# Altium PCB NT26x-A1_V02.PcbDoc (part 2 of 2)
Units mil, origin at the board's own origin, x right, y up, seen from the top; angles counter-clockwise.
Board outline 1026.77 x 2401.57 mil, 4 copper layers (Top Layer 1, GND2, POWER3, Bottom Layer 4), stack 61.855 mil thick; 87 components, 81 nets, 679 pads, 247 vias.
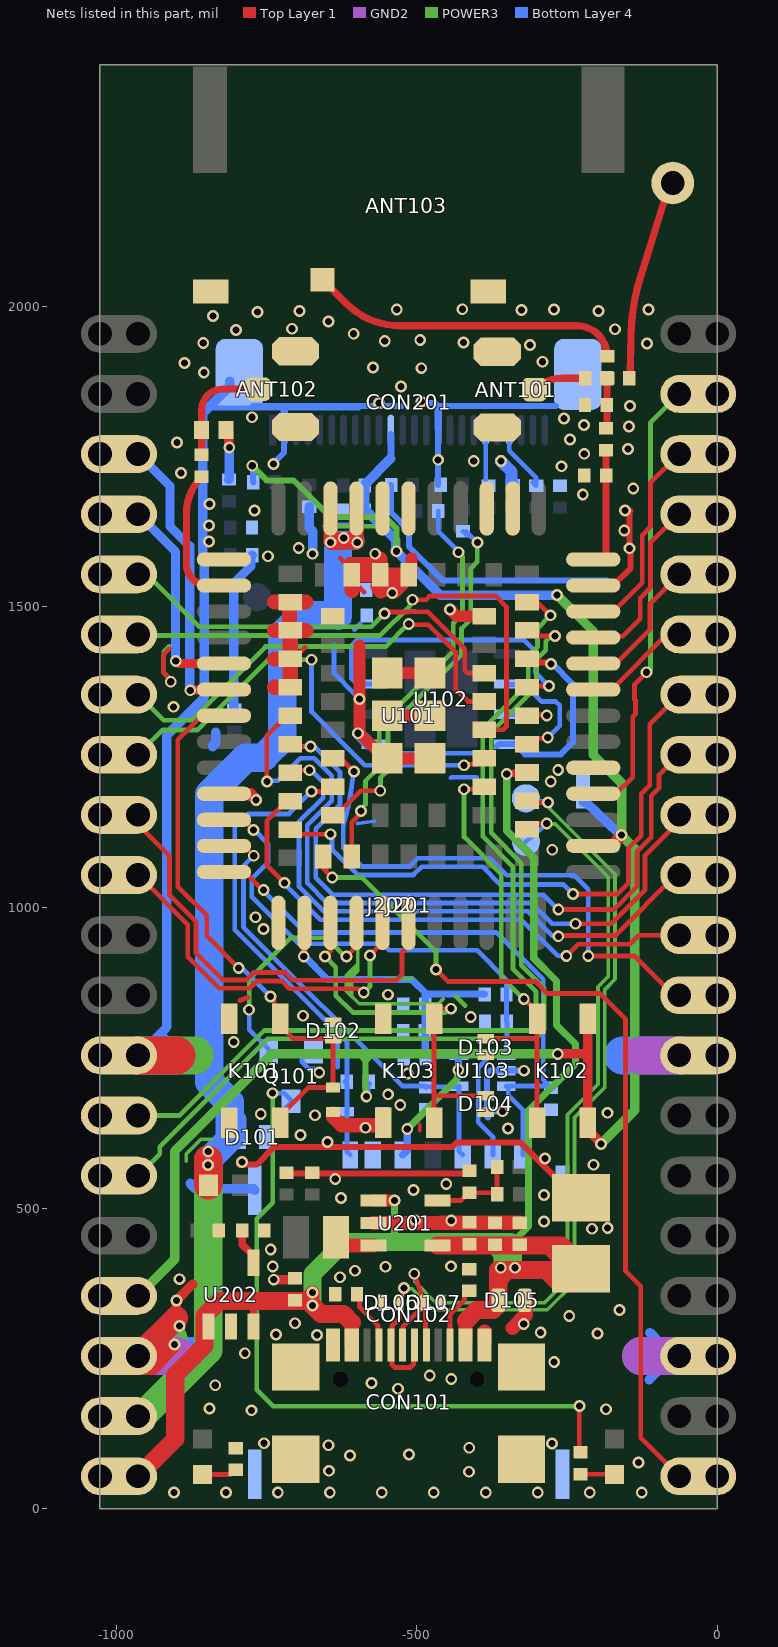
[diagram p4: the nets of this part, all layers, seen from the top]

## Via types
v1: diameter 19.68, hole 11.81, Top Layer 1 to Bottom Layer 4, tented both sides, 247 vias

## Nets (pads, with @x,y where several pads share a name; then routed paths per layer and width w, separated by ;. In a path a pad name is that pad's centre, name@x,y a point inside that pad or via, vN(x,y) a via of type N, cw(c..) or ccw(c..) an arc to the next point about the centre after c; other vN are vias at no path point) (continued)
GND: ANT101.2 ANT101.3 ANT102.2 ANT102.3 ANT103.2 C101.1 C102.1 C103.1 C104.1 C105.1 C109.1 C110.1 C112.1 C113.1 C114.1 C115.1 C116.1 C117.1 C118.1 C119.1 C202.1 C203.1 C204.2 C205.1 C206.1 C207.1 C208.1 C209.1 C210.1 C211.2 C212.2 C213.1 C214.1 C215.1 C216.1 CON101.0@-325.59,82.19 CON101.0@-325.59,235.73 CON101.0@-701.18,82.19 CON101.0@-701.18,235.73 CON101.A1B12 CON101.B1A12 CON102.0@-257.48,57.38 CON102.0@-257.48,529.82 CON102.0@-769.29,57.38 CON102.0@-769.29,529.82 CON102.5 CON201.0 CON201.2 CON201.15 D101.A D102.A D103.A D104.A D105.A D106.A D107.A D108.K J201.3 J201.8 J202.33 J202.38 K101.1 K101.2 K103.1 K103.2 P101.2 Q101.E R106.1 R107.1 R203.2 R204.2 U101.1@-820.47,1578.74 U101.10@-820.47,1188.98 U101.27@-206.3,1232.28 U101.34@-206.3,1535.43 U101.36@-340.16,1663.39 U101.37@-383.46,1663.39 U101.40@-513.39,1663.39 U101.41@-556.69,1663.39 U101.45@-710.24,1507.87 U101.46@-710.24,1460.63 U101.47@-710.24,1413.39 U101.48@-710.24,1366.14 U101.70@-513.39,1553.15 U101.71@-560.63,1553.15 U101.72@-607.87,1553.15 U101.73@-639.37,1484.25 U101.88@-387.4,1484.25 U101.89@-548.82,1389.76 U101.90@-548.82,1318.9 U101.91@-548.82,1248.03 U101.92@-477.95,1248.03 U101.93@-477.95,1318.9 U101.94@-477.95,1389.76 U101.95@-729.92,974.41 U102.1 U103.2 U201.2 U202.2 | length 8528.6
  Top Layer 1 w6: -494.92,639.05 -494.79,629
  Top Layer 1 w7.87: -911.09,1430.22 -920.47,1420.84 -920.47,1389.92 -909.04,1378.48 v1(-909.04,1375.29) ; U101.47@-700.03,1418.02 -685.89,1432.17 ; -627.03,1581.02 U101.72@-612.89,1566.88 ; U101.72@-601.81,1538.89 -587.67,1524.75
  Top Layer 1 w8: -794.05,845.19 -780.33,850.42
  Top Layer 1 w10: v1@-795.7,574.97 -795.7,572.35 -766.08,572.35 -736.52,601.92 -440.49,601.92 -433.72,608.68 -327,608.68 -235.32,517 C204.2@-226.46,517 ; C203.1@-716.6,557.45 -645.12,557.45 -644.69,557.87 -416.29,557.87 R203.2@-412.34,561.81 ; U101.88@-388.83,1485.68 U101.88@-387.4,1484.25 ; U101.34@-206.3,1535.43 -172.83,1535.43 -143.97,1564.3 -143.97,1574.3 -144.36,1574.69 -144.36,1595.37 v1(-146.22,1597.22) -146.22,1657.22 v1@-143.97,1659.46
  Top Layer 1 w11.81: J202.38@-987.07,228.5 -937.29,228.5 v1@-899.21,266.57 ; J202.38@-942.12,236.14 -913.15,265.11 ; J202.38@-941,247.71 -912.02,276.69
  Top Layer 1 w15.75: -899.66,317.66 v1(-899.66,346.39) -872.51,373.54 ; v1(-737.63,380.88) -704.66,380.88 C208.1@-702.2,383.34 C208.1@-700.17,385.38
  Top Layer 1 w19.68: v1(-444.48,1495.68) -433.06,1484.25 U101.88@-387.4,1484.25
  Top Layer 1 w20: U101.10@-820.47,1188.98 -819.78,1188.28 -776.32,1188.28 v1(-766.91,1178.88) ; U101.72@-611.33,1572.74 U101.71@-572.81,1572.74 ; -595.12,1435.38 v1(-595.12,1346.43) -595.12,1289.64 U101.91@-554.97,1249.49 ; U101.71@-560.01,1540.11 -566.82,1533.3 -560.32,1533.3 -560.01,1533 -552.91,1525.9 v1@-539.56,1525.9 ; U101.91@-548.82,1248.03 U101.92@-492.03,1248.03 ; U101.90@-548.82,1318.9 U101.93@-492.03,1318.9 ; U101.89@-548.82,1389.76 U101.94@-492.03,1389.76 ; -548.06,1530.92 -529.65,1549.33 ; v1@-536,1524.12 U101.70@-517.59,1542.53 ; U101.70@-508.61,1553.9 -508.61,1579.93
  Top Layer 1 w23.62: P101.2@-638.96,656.89 -638.96,651.63 -625.13,637.79 K103.1@-569.3,637.79 ; U201.2@-571.95,475.08 v1@-507.77,475.08 ; v1@-499.3,475.08 -459.74,475.08 -459.38,475.44 C206.1@-369.91,475.44 C205.1@-328.56,475.44 ; CON101.B1A12@-387.4,277.46 CON101.B1A12@-387.4,294.19 ; -340.66,300.62 -318.62,322.67 D105.A@-318.62,354.43
  Top Layer 1 w25: -736.27,1366.14 U101.48@-710.24,1366.14 U101.47@-710.24,1413.39 ; -736.27,1413.39 U101.47@-710.24,1413.39 ; -736.27,1460.63 U101.46@-711.67,1460.63 ; -736.27,1507.87 U101.45@-711.67,1507.87 ; U101.45@-711.67,1508.09 U101.45@-711.67,1507.87 ; -684.2,1460.63 U101.46@-710.24,1460.63 ; -684.2,1507.87 U101.45@-710.24,1507.87 U101.45@-711.67,1507.87 ; -607.87,1527.12 U101.72@-607.87,1553.15 U101.71@-560.63,1553.15 ; -560.63,1579.18 U101.71@-560.63,1553.15 ; -560.01,1526.5 -560.01,1533 -560.01,1540.11 -560.01,1552.53 U101.71@-560.63,1553.15 ; U101.71@-560.01,1553.15 U101.70@-513.39,1553.15 ; U101.46@-711.67,1460.63 U101.45@-711.67,1507.87 ; U101.46@-711.67,1460.63 U101.46@-710.24,1460.63 ; U101.47@-710.24,1413.39 U101.46@-710.24,1460.63
  Top Layer 1 w39.37: J202.38@-963.39,253.94 -899.66,317.66
  Top Layer 1 w62.99: J202.33@-963.39,753.94 -899.4,753.94
  GND2 w62.99: J202.38@-963.39,253.94 -899.4,253.94 ; J202.33@-963.39,753.94 -899.4,753.94 ; -127.37,253.94 J201.3@-63.39,253.94 ; -127.37,753.94 J201.8@-63.39,753.94
  POWER3 w5.98: -883.12,577.57 -883.12,589.86 -858.24,614.74 -840.88,614.74 ; -612.5,860.08 -612.5,886.39 ; -612.35,886.72 -602.16,896.92 ; -608.37,852.81 -608.37,883.66 -598.18,893.86 -598.18,905.86 ; -597.84,938.76 -598.08,938.53 -598.08,910.73 -598.18,910.63 -598.18,905.86 ; -547.93,881.07 -507.32,881.07 ; -456.24,847.77 -464.27,839.74 -595.71,839.74 -616.85,860.88 -616.85,887.19 -598.18,905.86
  POWER3 w7.87: -911.32,1434.27 -920.47,1425.12 -920.47,1389.92 -909.04,1378.48 v1(-909.04,1375.29) ; -652.9,1633.98 -561.16,1633.98 -551.08,1623.9 ; -435.32,852.29 -419.43,836.4
  POWER3 w51.18: J202.38@-975.53,249.42 -940.26,249.42 -906.72,282.97
  POWER3 w62.99: J202.33@-963.39,753.94 -869.46,753.94 ; -120.68,253.94 J201.3@-63.39,253.94
  Bottom Layer 4 w6: -598.75,1139.61 -569.89,1143.59
  Bottom Layer 4 w7.87: -844.62,1830.5 -724.62,1830.5 ; -715.54,1830.5 -595.53,1830.5 ; -652.9,1633.98 -650.51,1636.37 -590.08,1636.37 ; -637.36,1436.72 -637.36,1389.06 -603.12,1354.83 ; -603.62,1462.08 -594.21,1471.5 ; -536.18,1256.21 -399.96,1256.21 ; -442.71,1215.67 -442.01,1216.37 -400.27,1216.37
  Bottom Layer 4 w8: -690.89,747.15 -690.89,743.21 -679.14,731.46 -670.86,731.46 -665.12,725.71 v1(-661.95,725.71) ; -631.73,734.47 -631.73,771.84 ; -522.51,1491.75 -502.38,1491.75
  Bottom Layer 4 w10: CON201.0@-773.05,1833.55 -523.99,1833.55 ; v1(-738.09,1737.66) -738.09,1738.75 -720.27,1756.57 -720.27,1786.22 CON201.2@-720.08,1786.42 ; C213.1@-542.54,1702.63 -542.54,1656.71 -512.87,1627.04 -512.87,1600.18 -455.99,1543.3 -183.5,1543.3 -183.04,1543.76 ; v1(-492.17,1841.11) -490.31,1839.25 -469.88,1839.25 -464.17,1833.55 CON201.0@-267.94,1833.55 ; C214.1@-464.28,1702.4 -464.23,1702.45 v1(-464.23,1744.41) -464.23,1786.36 -464.17,1786.42 CON201.15@-464.17,1795.1 ; -381.62,650.83 -382.68,651.9 -382.68,724.1 -379.33,727.44 ; -376.82,660.93 v1(-357.45,660.93) ; -376.82,728.47 U103.2@-350.96,728.47 v1(-321.44,728.47)
  Bottom Layer 4 w12: CON201.2@-720.27,1786.61 -720.27,1831.86 ; CON201.15@-464.17,1795.1 -464.17,1827.49 -464.17,1831.2
  Bottom Layer 4 w15.75: J202.33@-981.61,730.94 -935.43,730.94 -914.44,751.93 ; J202.33@-963.39,768.84 -947.23,768.84 -917.39,798.68 ; J202.33@-937.02,747.74 -921.93,762.83 ; -933.73,766.35 -918.64,781.44 ; -915.37,801.95 -915.37,1286.68 -852.89,1349.16 -852.89,1585.52 -855.43,1588.06 -855.43,1635.2 -855.43,1822.33 -850.23,1827.52 -810.63,1867.13 CON201.0@-810.63,1875 ; -876.75,541.03 -867.53,531.8 -771.27,531.8 CON102.0@-769.29,529.82 ; -839.36,1267.43 -839.36,1268.91 -834.44,1273.83 -834.44,1291.45 ; C112.1@-804.09,1326.84 -804.09,1539.23 -775.9,1567.43 -775.9,1583.1 C104.1@-773.44,1585.56 ; C211.2@-678.68,1666.44 -678.4,1666.16 -678.4,1631.24 -673.14,1625.98 v1(-673.14,1588.08) ; -113.25,214.7 -98.16,229.79 ; -112.14,292.83 -97.05,277.73
  Bottom Layer 4 w20: v1(-597.7,1289.64) -597.47,1289.64 U102.1@-579.4,1271.57 ; v1(-359.79,1742.43) -359.79,1742.25 -341.93,1724.39 -341.93,1702.58 -341.59,1702.25 C215.1@-340.12,1702.25
  Bottom Layer 4 w62.99: J202.38@-963.39,253.94 -869.46,253.94 ; -157.31,753.94 J201.8@-63.39,753.94 ; J201.3@-91.82,253.94 J201.3@-63.39,253.94
  other v1: -903.8,26.8 -817.34,26.8 -730.89,26.8 -644.43,26.8 -557.97,26.8 -471.52,26.8 -385.06,26.8 -298.61,26.8 -212.15,26.8 -125.69,26.8 -412.9,61.4 -645.74,63.02 -131.05,76.87 -610.8,88.63 -512.49,90.13 -412.46,101.47 -646.41,105.5 -753.67,108.92 -274.74,108.56 -774.47,163.65 -185.01,165.41 -844.79,166.57 -530.9,199.57 -835.03,205.29 -575.34,209.09 -442.4,215.9 -478.18,221.36 -271.28,244.12 -785.77,258.48 -902.68,272.98 -665.46,288.96 -734.18,289.65 -199,291.21 -293.74,293.07 -894.69,303.78 -321.85,307.06 -702.47,308.48 -246.16,320.54 -162.86,330.24 -894.3,381.74 -627.26,385.01 -602.78,395.79 -552.05,402.33 -739.25,403.09 -443.09,403.14 -742.77,431.15 -208.25,465.67 -182.31,466.66 -288.21,477.9 -442.48,479.06 -502.38,479.83 -625.75,516.77 -288.21,521.77 -505.1,529.85 -450.86,540.28 -635.36,548.45 -206.15,572.01 -790.23,576.52 -286.49,582.16 -648.16,609.97 -693.08,621.29 -348.22,632.55 -585,633.63 -669.21,654.32 -759.27,656.59 -182.68,658.43 -527.22,671.66 -547.37,689.17 -514.9,723.71 -804.16,776.08 -410.06,817.85 -689.09,819.81 -547.51,854.87 -754.5,964.01 -768.25,983.62 -274.47,1095.88 -276.94,1209.3 -264.61,1228.8 -904.45,1333.61 -540.65,1522.75 -747.1,1583.98 -568.97,1588.13 -696.05,1597.67 -845.5,1608.42 -154.73,1626.73 -845.32,1635.2 -769.73,1660.3 -153.56,1660.26 -844.79,1670.79 -223.67,1686.7 -139.71,1696.65 -891.82,1722.49 -258.98,1733.59 -405.04,1742.43 -221.33,1754.36 -148.47,1762.41 -898.82,1772.95 -244.85,1778.39 -146.8,1799.66 -221.84,1802.17 -255.16,1813.17 -773.77,1815.24 -145.11,1834.1 -562.88,1839.1 -526.12,1866.59 -854,1889.48 -492.27,1896.81 -572.5,1897.9 -886.25,1905.58 -290.63,1907.47 -311.44,1935.53 -854.96,1938.4 -116.93,1937.76 -421.98,1939.28 -553.11,1941.97 -494.12,1943.66 -604.75,1954.06 -800.58,1960.47 -170.4,1961.49 -707.22,1962.4 -646.51,1974.23 -838.89,1983.62 -764.51,1990.25 -694.93,1992.09 -197.56,1991.93 -325.58,1993.53 -533.17,1994.47 -271.61,1994.35 -424.07,1994.87 -114.39,1994.55
I2C_SCL: J202.34 U101.67@-316.54,1507.87 | length 1571
  Top Layer 1 w7.87: U101.67@-308.89,1500.22 U101.67@-316.54,1507.87 -299.72,1507.87 v1(-277.64,1485.79)
  POWER3 w7.87: J202.34@-995.08,653.94 J202.34@-979.23,669.78 ; J202.34@-963.39,653.94 -894.85,653.94 -753.48,795.31 -309.09,795.31 -301.46,802.94 -301.46,859.93 -339.78,898.25 -339.78,1067.87 -389.99,1118.07 -389.99,1296.69 -314.56,1372.11 -314.56,1417.78 -298.99,1433.35 -298.99,1464.44 v1(-277.64,1485.79)
I2C_SDA: J202.35 U101.66@-316.54,1460.63 | length 1573
  Top Layer 1 w7.87: U101.66@-316.54,1460.63 -307.16,1451.25 v1(-269.73,1451.25)
  POWER3 w7.87: J202.35@-963.39,553.94 -927.44,589.88 -927.44,601.75 -747.74,781.45 -303.17,781.45 -287.61,797.01 -287.61,865.67 -325.92,903.99 -325.92,1073.61 -376.13,1123.81 -376.13,1290.95 -300.7,1366.37 -300.7,1412.04 -285.13,1427.61 -285.13,1442.56 -278.69,1448.99 -271.99,1448.99 v1(-269.73,1451.25)
I2S_BCK: J201.15 U101.30@-206.3,1362.2 | length 195.8
  Top Layer 1 w7.87: U101.30@-206.3,1362.2 -175.79,1362.2 -84.05,1453.94 J201.15@-63.39,1453.94 J201.15@-73.93,1443.39
I2S_DIN: J201.17 U101.32@-206.3,1448.82 | length 291.6
  Top Layer 1 w7.87: U101.32@-206.3,1448.82 -204.02,1451.09 -157.45,1451.09 -128.12,1480.43 -128.12,1514.51 -111.13,1531.5 -111.13,1606.19 J201.17@-63.39,1653.94
I2S_DOUT: J201.18 U101.33@-206.3,1492.13 | length 340.6
  Top Layer 1 w7.87: U101.33@-206.3,1492.13 -172.83,1492.13 -124.99,1539.97 -124.99,1619.26 -111.13,1633.12 -111.13,1706.19 J201.18@-63.39,1753.94
I2S_LRCK: J201.16 U101.31@-206.3,1405.51 | length 229.5
  Top Layer 1 w7.87: U101.31@-206.3,1405.51 -168.89,1405.51 -111.91,1462.49 -111.91,1505.41 J201.16@-63.39,1553.94
I2S_MCLK: J201.19 U101.26@-206.3,1188.98 | length 749
  Top Layer 1 w7.87: U101.26@-206.3,1188.98 -168.57,1188.98 -140.79,1216.76 -140.79,1317.02 -135.97,1321.84 -135.97,1344.03 -137.58,1345.64 -137.58,1371.02 v1(-117.56,1391.04)
  POWER3 w7.87: v1(-117.56,1391.04) -115.21,1391.04 -111.13,1395.12 -111.13,1806.19 J201.19@-63.39,1853.94
LCD_CLK: J201.14 U101.53@-710.36,1129.47 | length 992
  Top Layer 1 w7.87: U101.53@-710.36,1129.47 -702.68,1121.79 v1(-643.13,1121.79) ; v1(-240.1,1022.46) -165.95,1022.46 -147.88,1040.53 -147.88,1097.99 -126.27,1119.59 -126.27,1189.05 -112.38,1202.94 -112.38,1304.94 -70.85,1346.47 -70.85,1353.94 J201.14@-63.39,1353.94
  Bottom Layer 4 w7.87: v1(-643.13,1121.79) -640.87,1119.53 -640.87,1096.53 -598.33,1054 -505.43,1054 -491.58,1067.84 -390.48,1067.84 -360.75,1038.11 -255.75,1038.11 v1(-240.1,1022.46)
LCD_CS: J201.10 U101.52@-710.36,1176.72 | length 921.2
  Top Layer 1 w7.87: v1(-719.9,1040.92) -748.94,1069.96 -748.94,1144.04 -716.27,1176.72 U101.52@-710.36,1176.72 ; v1(-251.1,919.05) -231.28,938.87 -145.67,938.87 -130.61,953.94 J201.10@-63.39,953.94 J201.10@-31.69,953.94
  Bottom Layer 4 w7.87: v1(-719.9,1040.92) -719.9,1039.5 -660,979.61 -325.69,979.61 -265.55,919.47 -251.52,919.47 v1(-251.1,919.05)
LCD_DOUT: J201.13 U101.50@-710.36,1271.2 | length 1115.4
  Top Layer 1 w7.87: U101.50@-710.36,1271.2 -705.82,1266.66 -704.69,1267.79 v1(-676.7,1267.79) ; v1(-264.39,996.38) -172.42,996.38 -134.02,1034.79 -134.02,1092.25 -109.92,1116.34 -109.92,1185.8 -96.79,1198.93 -96.79,1220.53 J201.13@-63.39,1253.94
  Bottom Layer 4 w7.87: v1(-676.7,1267.79) -670.5,1267.79 -627.43,1224.72 -627.43,1171.25 -667.99,1130.69 -667.99,1049.58 -639.6,1021.18 -289.19,1021.18 v1(-264.39,996.38)
LCD_RS: J201.11 U101.51@-710.36,1223.96 | length 967.5
  Top Layer 1 w7.87: U101.51@-710.36,1223.96 -706.21,1228.11 v1(-678.37,1228.11) ; v1@-266.01,958.91 -260.22,953.12 -170.14,953.12 -69.32,1053.94 J201.11@-63.39,1053.94
  Bottom Layer 4 w7.87: v1(-678.37,1228.11) -675.46,1228.11 -655.14,1207.79 -655.14,1182.73 -695.71,1142.17 -695.71,1034.91 -654.26,993.46 -314.98,993.46 -273.44,951.93 v1(-264.39,951.93)
LCD_RST: J201.12 U101.49@-710.36,1318.45 | length 1258.6
  Top Layer 1 w7.87: v1(-749.1,1209.51) -749.33,1209.74 -749.33,1285.39 -716.27,1318.45 U101.49@-710.36,1318.45 ; v1(-235.6,972.88) -176.32,972.88 -120.16,1029.05 -120.16,1086.51 -63.39,1143.28 J201.12@-63.39,1153.94 ; J201.12@-62.77,1138.09 -47.54,1138.09 J201.12@-31.69,1153.94
  Bottom Layer 4 w7.87: v1(-749.1,1209.51) -747.94,1210.67 -731.02,1210.67 -693.66,1248.03 -670.33,1248.03 -641.29,1218.98 -641.29,1176.99 -681.85,1136.43 -681.85,1040.65 -648.52,1007.32 -309.24,1007.32 -274.8,972.88 v1(-235.6,972.88)
LCD_TE: J201.9 U101.78@-639.37,1248.03 | length 963.7
  Top Layer 1 w7.87: U101.78@-629.68,1238.34 U101.78@-639.37,1248.03 -626.64,1248.03 v1(-604.4,1225.79) ; v1@-220.43,919.11 v1(-214.62,919.11) -137.39,919.11 -72.22,853.94 J201.9@-63.39,853.94 J201.9@-31.69,853.94
  Bottom Layer 4 w7.87: v1@-604.4,1222.59 v1(-604.4,1225.79) -610.97,1182.61 -612.15,1174.86 -614.89,1164.16 -621.96,1136.57 -621.96,1098.82 -591.24,1068.11 -511.63,1068.11 -498.04,1081.7 -378.04,1081.7 -349.93,1053.59 -238.06,1053.59 -214.62,1030.15 v1(-214.62,919.11)
MAIN_RXD: J202.30 U101.17@-556.69,974.41 | length 628.1
  Top Layer 1 w7.87: J202.30@-963.39,1053.94 -880.87,971.42 -880.87,917.97 -828.28,865.38 -777.85,865.38 -765.43,877.8 -724.55,877.8 -711.58,864.84 -597.39,864.84 -591.11,858.56 v1(-587.91,858.56) ; v1@-579.51,919.94 -578.6,919.94 -556.69,941.85 U101.17@-556.69,974.41
  POWER3 w7.87: v1(-587.91,858.56) -587.91,858.69 -577.53,869.08 v1(-577.53,919.94)
MAIN_TXD: J202.29 U101.18@-513.39,974.41 | length 764.9
  Top Layer 1 w7.87: J202.29@-995.08,1153.94 -979.17,1153.94 -979.17,1142.8 -967.52,1131.15 -956.38,1131.15 -911.1,1085.87 -911.1,1021.25 -867.01,977.16 -867.01,924.39 -821.86,879.24 -783.59,879.24 -771.17,891.66 -718.8,891.66 -705.84,878.7 -534.08,878.7 -524.29,888.49 -524.29,925.77 -513.39,936.68 U101.18@-513.39,974.41
NET_STATUS: Q101.B U101.16@-600,974.41 | length 429.1
  Top Layer 1 w7.87: v1@-616.9,921.29 v1(-616.9,918.52) -600,935.42 U101.16@-600,959.31 ; U101.16@-603.01,971.4 U101.16@-600,974.41 U101.16@-600,938.18
  POWER3 w7.87: v1(-778.56,829.81) -778.56,880.62 -709.42,949.77 -650.59,949.77 v1@-616.9,916.07
  Bottom Layer 4 w7.87: v1(-778.56,829.81) -778.56,796.81 -746.03,764.28 Q101.B@-746.03,760.34
NetANT101_1: ANT101.1 C106.2 | length 94.2
  Top Layer 1 w12: ANT101.1@-303.94,1861.19 cw(c-258.55,1815.81) -258.55,1879.99 C106.2@-219.43,1879.99 C106.2@-223.77,1878.17
NetANT102_1: ANT102.1 C111.1 L101.1 | length 188.4
  Top Layer 1 w12: C111.1@-857.58,1752.71 -857.58,1827.25 cw(c-822.88,1827.25) -822.88,1861.96 ANT102.1@-763.5,1861.96
NetANT103_1: ANT103.1 C108.1 | length 529.2
  Top Layer 1 w12: ANT103.1@-656.69,2044.08 -616.77,2004.16 ccw(c-528.27,2092.66) -528.27,1967.5 -234.11,1967.5 cw(c-234.11,1916.41) C108.1@-183.02,1916.41
NetANT104_1: ANT104.1 C120.2 | length 337.2
  Top Layer 1 w12: C120.2@-146.6,1879.99 -144.7,1885.8 -144.7,1886.07 -143.62,1954.44 -143.62,1954.59 cw(c229.61,1939.82) -127.02,2050.87 -80.7,2199.61 -77.32,2202.99 -75.7,2203.84 ANT104.1@-74.02,2204.72
NetC106_1: C106.1 C107.1 C108.2 C110.2 C120.1 | length 84.3
  Top Layer 1 w12: C107.1@-185.18,1796.55 -183.57,1798.16 C110.2@-183.57,1835.65 -183.29,1835.93 -183.29,1879.71 C120.1@-183.02,1879.99
NetC107_2: C107.2 C109.2 U101.35@-206.3,1578.74 | length 198.3
  Top Layer 1 w12: U101.35@-206.3,1578.74 -192.45,1578.74 -185.18,1586.01 C107.2@-185.18,1760.14
NetC111_2: C111.2 U101.2@-820.47,1535.43 | length 234.8
  Top Layer 1 w12: C111.2@-857.58,1716.29 ccw(c-796.3,1655) -882.97,1655 -882.97,1571.21 ccw(c-847.19,1571.21) -847.19,1535.43 U101.2@-820.47,1535.43
NetC201_1: C201.1 R202.1 R203.1 U201.5 | length 150.7
  Top Layer 1 w7.87: U201.5@-465.65,512.48 -426.73,512.48 -413.82,525.4 R203.1@-412.34,525.4 -368.57,525.4 -366.28,523.11 C201.1@-366.28,568.06
NetC210_2: C210.2 U202.4 | length 61.4
  Top Layer 1 w11.81: C210.2@-789.99,462.86 -789.99,439.04 -775.74,424.8 -771.65,420.71 U202.4@-771.65,409.05
NetCON101_A5: CON101.A5 R106.2 | length 81.6
  Top Layer 1 w7.87: R106.2@-594.87,345.72 -594.87,335.1 -564.47,304.7 -564.47,279.33 CON101.A5@-562.6,277.46
NetCON101_B5: CON101.B5 R107.2 | length 98.8
  Top Layer 1 w7.87: CON101.B5@-444.49,277.46 -444.49,323.1 -420.41,347.18 -420.41,355.75 -414.01,362.15 R107.2@-412.54,362.15
NetCON201_19: CON201.19 R207.2 | length 87.2
  Bottom Layer 4 w7.87: CON201.19@-385.43,1786.42 -385.24,1786.22 -385.24,1706.24 R207.2@-380.3,1701.31
NetCON201_21: CON201.21 R208.2 | length 111.9
  Bottom Layer 4 w7.87: CON201.21@-346.06,1786.42 -345.87,1786.22 -345.87,1759.71 -300.97,1714.81 R208.2@-300.97,1701.51 -301.77,1701.51 R208.2@-307.11,1706.84
NetL101_2: L101.2 R101.1 | length 87.5
  Top Layer 1 w10: v1(-811.56,1764.62) v1@-809.71,1766.47
  Top Layer 1 w15.75: L101.2@-817.21,1793.92 -812.78,1789.49 -812.78,1766.9 -811.56,1765.68 v1(-811.56,1764.62)
  Bottom Layer 4 w15.75: R101.1@-812.28,1711.65 -811.92,1712.01 -811.92,1764.26 v1(-811.56,1764.62)
NetL201_1: L201.1 U201.3 | length 74.7
  Top Layer 1 w23.62: L201.1@-633.57,471.39 -635.74,469.22 -635.74,465.66 L201.1@-625.9,455.82 ; L201.1@-626.09,437.68 U201.3@-571.95,437.68
NetLED101_K: LED101.K R103.1 | length 56.5
  Top Layer 1 w7.87: R103.1@-227.75,57.49 LED101.K@-171.27,57.49
NetLED201_K: LED201.K R204.1 | length 58.2
  Top Layer 1 w7.87: LED201.K@-855.91,57.09 -809.65,57.09 -802.26,64.47 R204.1@-800.79,64.47
NetQ101_C: Q101.C R103.2 | length 1185.1
  Top Layer 1 w7.87: v1(-229.39,170.55) -229.39,95.55 R103.2@-227.75,93.9
  POWER3 w7.87: v1@-739.5,691.05 -739.5,509.04 -766,482.55 -766,197.96 -738.6,170.55 v1(-229.39,170.55)
  Bottom Layer 4 w7.87: v1(-739.84,691.05) -720.44,691.05 -708.63,679.24 Q101.C@-708.63,677.67 -708.63,676.28 Q101.C@-720.44,664.47
NetR102_2: R102.2 U101.80@-639.37,1153.54 | length 611.2
  Top Layer 1 w7.87: U101.80@-639.37,1153.54 -633.46,1153.54 -593.01,1194 v1(-560.62,1194)
  POWER3 w7.87: v1(-560.62,1194) -560.19,1194.43 -560.19,1215.65 -547.53,1228.32 -547.53,1298.17 -425.43,1420.27 -425.43,1463.71 -410.03,1479.1 -410.03,1563.6 -399.09,1574.54 v1(-399.09,1607)
  Bottom Layer 4 w7.87: R102.2@-422.93,1625.37 R102.2@-416.53,1618.97 ; R102.2@-417.46,1625.37 -417.46,1624.11 -415.06,1621.7 -413.8,1621.7 v1(-399.09,1607)
NetR104_2: R104.2 U101.54@-607.87,1084.65 | length 673.2
  Top Layer 1 w7.87: U101.54@-607.87,1084.65 -607.87,1142.05 -592.44,1157.48 v1(-592.44,1160.1)
  POWER3 w7.87: v1(-592.44,1160.1) -592.44,1163.29 -585.2,1170.54 -585.2,1210.25 -562.37,1233.08 -562.37,1302.93 -439.28,1426.01 -439.28,1472.93 -423.89,1488.33 -423.89,1584.05 v1(-430.58,1590.75) v1@-430.58,1587.55
  Bottom Layer 4 w7.87: R104.2@-464.01,1659.2 -464.01,1625.47 -430.58,1592.04 v1(-430.58,1590.75)
  Bottom Layer 4 w10: v1(-592.44,1160.1) v1@-589.82,1160.1
PWRKEY: D102.K K101.3 K101.4 P101.1 U101.7@-820.47,1318.9 | length 917.9
  Top Layer 1 w7.87: U101.7@-820.47,1318.9 -857.33,1318.9 -897.25,1278.98 -897.25,1034.57 -849.27,986.6 -849.27,952.54 v1(-795.96,899.23) ; v1(-743.09,852.04) -743.09,851.12 -736.81,844.84 -736.81,824.8 K101.4@-726.97,814.96 -726.97,803.15 -705.35,781.53 D102.K@-638.96,781.53 P101.1@-638.96,700.35 -680.16,700.35 -717.13,663.39 K101.3@-717.13,660.14
  Bottom Layer 4 w7.87: v1(-795.96,899.23) -793.7,896.97 -788.03,896.97 v1(-743.09,852.04)
RESET_N: D104.K K103.3 K103.4 U101.15@-643.31,974.41 | length 641.1
  Top Layer 1 w7.87: v1@-652.33,921.72 v1(-652.33,918.52) -643.31,927.54 U101.15@-643.31,974.41 U101.15@-646.32,971.4 ; K103.3@-471.06,641.73 K103.4@-471.06,814.96 -471.06,821.77 -461.22,831.61 v1(-442.71,831.61) ; -468.23,686.9 D104.K@-385.13,686.9
  POWER3 w7.87: v1(-652.33,918.52) -634.4,900.59 -634.4,853.42 -606.35,825.38 -452.14,825.38 -445.9,831.61 v1(-442.71,831.61)
SPI_CS: J202.28 U101.83@-387.4,1248.03 | length 769.6
  Top Layer 1 w7.87: v1(-421.17,1236.44) -419.42,1238.19 -397.24,1238.19 U101.83@-387.4,1248.03
  POWER3 w7.87: J202.28@-963.39,1253.94 -922.18,1295.14 -863.87,1295.14 -747.17,1411.84 v1(-674.72,1411.84)
  Bottom Layer 4 w7.87: v1(-674.72,1411.84) -674.72,1325.13 -619.71,1270.11 -586.04,1236.44 v1(-421.17,1236.44)
SPI_MISO: J202.26 U101.84@-387.4,1295.28 | length 890
  Top Layer 1 w7.87: v1(-506.99,1511.66) -484.34,1511.66 -477.89,1518.11 -368.81,1518.11 -350.69,1499.99 -350.69,1300.5 -355.92,1295.28 U101.84@-387.4,1295.28
  POWER3 w7.87: J202.26@-963.39,1453.94 -961.72,1452.27 -560.39,1452.27 -511.43,1501.23 -511.43,1504.03 -506.99,1508.47 v1(-506.99,1511.66)
SPI_MOSI: J202.27 U101.85@-387.4,1342.52 | length 749.6
  Top Layer 1 w7.87: v1(-513.21,1471.49) -512.03,1470.3 -480.83,1470.3 -435.13,1424.61 -435.13,1363.07 -414.59,1342.52 U101.85@-387.4,1342.52
  POWER3 w7.87: J202.27@-963.39,1353.94 -920.55,1311.1 -874.11,1311.1 -751.34,1433.87 -551.3,1433.87 -513.69,1471.49 v1(-513.21,1471.49)
SPI_SCLK: J202.25 U101.86@-387.4,1389.76 | length 717.4
  Top Layer 1 w7.87: v1(-553.34,1489.03) -551.12,1491.25 -515.1,1491.25 -514.45,1491.9 -481.62,1491.9 -419.96,1430.24 -419.96,1394.38 -415.35,1389.76 U101.86@-387.4,1389.76
  POWER3 w7.87: J202.25@-995.08,1553.94 -948.47,1553.94 -861.41,1466.88 -575.5,1466.88 v1(-553.34,1489.03)
SPK_N: J202.23 U101.6@-820.47,1362.2 | length 485.7
  Top Layer 1 w7.87: U101.6@-820.86,1362.59 U101.6@-820.47,1362.2
  Top Layer 1 w15: v1(-876.59,1361.06) -876.02,1361.63 -821.82,1361.63 U101.6@-820.86,1362.59
  Bottom Layer 4 w15: J202.23@-963.39,1753.94 -910.42,1700.97 -910.42,1633.99 -877.38,1600.95 -877.38,1361.86 v1(-876.59,1361.06)
SPK_P: J202.24 U101.5@-820.47,1405.51 | length 352.3
  Top Layer 1 w7.87: U101.5@-820.62,1405.36 U101.5@-820.47,1405.51
  Top Layer 1 w15: v1(-900.71,1409.73) -899.44,1409.73 -895.23,1405.52 -820.78,1405.52 U101.5@-820.62,1405.36
  Bottom Layer 4 w15: J202.24@-963.39,1653.94 -900.71,1591.26 v1(-900.71,1409.73)
USB_BOOT: D103.K K102.1 K102.2 U101.82@-387.4,1200.79 | length 727
  Top Layer 1 w7.87: v1(-421.06,1196.61) -391.58,1196.61 U101.82@-387.4,1200.79 ; D103.K@-385.13,781.45 -300.34,781.45 -299.8,781.98 ; v1(-321.77,847.89) -320.92,847.89 -299.8,826.77 -299.8,781.98 ; K102.1@-299.8,641.73 -299.8,781.98
  POWER3 w7.87: v1(-421.06,1196.61) -421.17,1196.5 -421.17,1117.18 -359.2,1055.21 -359.2,884.74 -322.36,847.89 v1(-321.77,847.89)
USB_DN: CON101.A7 CON101.B7 D106.K TP102.1 U101.60@-316.54,1177.16 | length 1473.6
  Top Layer 1 w8: v1(-521.15,366.83) -524.95,352.44 D106.K@-528.82,342.66 -528.82,316.13 -541.01,303.95 -541.01,239.85 -536.25,235.09 -510.21,235.09 -505.45,239.85 -505.45,275.56 CON101.A7@-503.54,277.46 ; U101.60@-316.54,1177.16 -300.85,1174.66 v1(-281.44,1174.66)
  POWER3 w6: v1(-521.15,366.83) -520.04,365.73 -507.6,365.73 -472.87,330.99 -282.59,330.99 -237.56,376.03 -237.56,650.51 -186.93,701.14 -186.93,863.55 -170.09,880.39 -170.09,1055.37 -278.82,1164.09 -278.82,1172.04 v1(-281.44,1174.66)
  Bottom Layer 4 w8: TP102.1@-318.2,1181.4 v1(-281.44,1174.66)
USB_DP: CON101.A6 CON101.B6 D107.K TP103.1 U101.59@-316.54,1129.92 | length 1422.9
  Top Layer 1 w8: CON101.A6@-523.23,272.15 -523.23,302.64 D107.K@-485.18,340.69 ; v1(-503.96,390.78) -490.37,352.27 D107.K@-486.49,342.49 -485.18,341.18 D107.K@-485.18,340.69 ; CON101.B6@-483.86,272.15 -485.18,273.46 D107.K@-485.18,340.69 ; U101.59@-316.54,1129.92 -300.85,1139.29 v1(-283.65,1139.29)
  POWER3 w6: v1(-503.96,390.78) -502.85,389.68 -502.85,377.24 -468.11,342.49 -287.36,342.49 -249.06,380.79 -249.06,655.27 -198.43,705.91 -198.43,868.31 -181.59,885.15 -181.59,1050.6 -269.64,1138.65 -283.01,1138.65 v1(-283.65,1139.29)
  Bottom Layer 4 w8: TP103.1@-318.19,1109.37 v1(-283.65,1139.29)
USIM2_CLK: U101.62@-316.54,1271.65 U102.6 | length 203.2
  Top Layer 1 w7.87: U101.62@-316.54,1271.65 -306.69,1281.5 -283.17,1281.5 v1(-281.95,1282.72)
  Bottom Layer 4 w7.87: U102.6@-349.4,1371.57 -348.71,1370.88 -320.55,1370.88 -292.09,1342.42 -268.52,1342.42 -262.04,1335.94 -262.04,1301.83 -281.15,1282.72 v1(-281.95,1282.72)
USIM2_DATA: U101.64@-316.54,1366.14 U102.3 | length 519.9
  Top Layer 1 w7.87: U101.64@-316.54,1366.14 -314.55,1368.12 v1(-280,1368.12)
  Bottom Layer 4 w7.87: U102.3@-569.87,1371.57 -599.71,1371.57 -608.94,1380.8 -608.94,1435.24 -599.53,1444.65 -321.2,1444.65 -302.59,1426.05 -302.59,1390.72 v1(-280,1368.12)
USIM2_RST: U101.63@-316.54,1318.9 U102.7 | length 99.8
  Top Layer 1 w7.87: U101.63@-316.54,1318.9 -316.05,1319.38 v1(-283.6,1319.38)
  Bottom Layer 4 w7.87: U102.7@-349.4,1321.57 -348.31,1320.47 -284.69,1320.47 v1(-283.6,1319.38)
USIM2_VDD: U101.65@-316.54,1413.39 U102.8 | length 333.8
  Top Layer 1 w10: U101.65@-316.54,1413.39 -315.77,1412.62 -310.55,1407.4 -278.77,1407.4 v1(-276.44,1405.07)
  Bottom Layer 4 w10: U102.8@-366.05,1268.69 -363.18,1271.57 -335.62,1271.57 -332.75,1268.69 -332.75,1267.46 -319.79,1254.5 -260.1,1254.5 -240.2,1274.4 -240.2,1371.45 -273.82,1405.07 v1(-276.44,1405.07)
USIM_CLK: C119.2 CON102.3 U101.13@-820.47,1059.05 U103.3 | length 982.5
  Top Layer 1 w7.87: U101.13@-820.47,1059.05 -785.8,1059.05 -755.6,1028.85 v1(-754.39,1028.85)
  Bottom Layer 4 w7.87: v1(-754.39,1028.85) -754.39,1026.68 -686.12,958.41 -367.42,958.41 -289.42,880.41 -289.42,713.01 -284.29,707.87 -284.29,706.4 -283.27,705.38 -281.79,705.38 C119.2@-276.42,700 ; U103.3@-350.96,702.88 -347.72,699.63 -347.72,687.8 -323.23,663.31 CON102.3@-323.23,588.29 ; U103.3@-347.72,702.88 C119.2@-284.29,702.88
USIM_DATA: C114.2 CON102.7 R105.1 U101.11@-820.47,1145.67 U103.1 | length 1007.6
  Top Layer 1 w7.87: U101.11@-820.47,1145.67 -817.46,1142.66 -784.68,1142.66 -771.5,1129.47 v1(-771.5,1128.78)
  Bottom Layer 4 w7.87: v1(-771.5,1128.78) -770.2,1128.78 -747.28,1105.86 -747.28,1074.53 -774.16,1047.66 -774.16,1017.47 -696.39,939.71 -556.21,939.71 -545.36,928.85 -399.57,928.85 -350.6,879.88 R105.1@-350.6,855.32 ; CON102.7@-373.23,588.29 -373.23,618.54 -397.6,642.91 -397.6,733.28 -376.83,754.06 -349.85,754.06 C114.2@-349.89,809.93 ; R105.1@-350.73,855.19 -350.73,810.77 C114.2@-349.89,809.93
USIM_DET: CON102.CD D108.A R108.2 U101.79@-639.37,1200.79 | length 818.8
  Top Layer 1 w7.87: v1(-675.02,1192.84) -647.32,1192.84 U101.79@-639.37,1200.79
  Bottom Layer 4 w7.87: v1(-675.02,1192.84) -712.45,1155.42 -780.55,1155.42 -802.66,1133.3 -802.66,962.46 -615.69,775.49 -615.69,713.85 -619.28,710.26 -615.69,706.67 -615.69,660.36 -615.69,593.35 CON102.CD@-610.63,588.29
USIM_RST: C118.2 CON102.2 U101.12@-820.47,1102.36 U103.4 | length 769.2
  Top Layer 1 w7.87: U101.12@-820.47,1102.36 -787.16,1102.36 -770.92,1086.13 v1(-770.92,1085.98)
  Bottom Layer 4 w7.87: v1(-770.92,1085.98) -788.01,1068.88 -788.01,967.41 -523.66,703.05 -486.84,703.05 C118.2@-484.25,700.47 -483.05,701.67 -430.91,701.67 U103.4@-429.7,702.88 -429.7,594.76 CON102.2@-423.23,588.29
USIM_VDD: C115.2 C116.2 C117.2 CON102.1 R105.2 U101.14@-686.61,974.41 U103.5 | length 744.7
  Top Layer 1 w11.81: v1@-687.76,919.94 -687.19,920.52 -687.19,973.84 U101.14@-686.61,974.41
  POWER3 w11.81: v1(-515.72,631.76) -432.07,715.42 -432.07,728.08 v1(-430.72,729.43)
  Bottom Layer 4 w11.81: v1@-687.76,919.94 -648.11,880.29 -508.14,880.29 -483.6,855.75 ; CON102.1@-523.23,588.29 -515.72,595.79 v1(-515.72,631.76) ; C115.2@-486.04,838.01 -486.04,794.17 -485.76,793.9 -485.76,757.59 -482.23,754.06 U103.5@-432.04,754.06 ; C115.2@-485.63,838.01 -485.63,855.75 -483.6,855.75 ; v1(-430.72,729.43) -430.21,729.94 -430.21,752.23 U103.5@-432.04,754.06 ; U103.5@-429.7,754.06 U103.5@-432.04,754.06 ; R105.2@-387.45,855.75 -483.6,855.75
  other v1: -687.76,918.52
VBAT: C101.2 C102.2 C103.2 D101.K J202.39 R201.2 U101.42@-600,1663.39 U101.43@-643.31,1663.39 | length 2257.7
  Top Layer 1 w23.62: v1@-643.31,1607.61 U101.43@-643.31,1629.51 ; U101.43@-643.31,1629.92 U101.43@-643.31,1663.39 ; v1@-641.5,1606.52 v1@-619.61,1606.52 ; -633.04,1612.69 -611.15,1612.69 ; v1@-623.29,1606.72 v1@-601.39,1606.72 ; U101.42@-600,1663.39 -600,1608.29 v1(-598.87,1607.16)
  Top Layer 1 w31.5: J202.39@-963.39,153.94 J202.39@-963.39,158.84
  Top Layer 1 w47.24: R201.2@-846.76,538.25 v1(-846.76,571.87) v1@-846.76,580.47
  POWER3 w31.5: J202.39@-995.08,153.94 J202.39@-963.39,153.94 J202.39@-956.61,153.94
  POWER3 w47.24: J202.39@-956.61,153.94 -846.76,263.79 v1(-846.76,571.87) v1@-846.76,580.12
  Bottom Layer 4 w7.87: -637.89,1590.74 -649.58,1602.43 -649.58,1609.92 -637.97,1621.54 v1@-623.63,1621.54 ; -623.9,1589.09 -611.58,1601.41
  Bottom Layer 4 w15.75: v1@-844.04,574.91 -807.77,611.18 ; v1@-839.29,589.81 D101.K@-803.02,626.07 ; -798.43,647.73 -798.72,647.45 -810.69,635.47 -849.49,596.68 -849.49,566.52 -839.28,566.52 D101.K@-797.8,608
  Bottom Layer 4 w23.62: -691.59,1486.04 -684.11,1486.04 -683.71,1485.65 ; -631.67,1485.65 -630.85,1484.83
  Bottom Layer 4 w31.5: D101.K@-798.72,621.67 -798.72,647.45 ; v1@-628.92,1609.87 v1@-602.33,1609.87
  Bottom Layer 4 w47.24: -810.69,621.03 -810.69,635.47 -810.69,675.83 -845.08,710.21 -845.08,1188.27 -784.29,1249.05 -759.25,1249.05 ; -753.79,1250.86 -723.25,1281.4 -723.25,1454.38 -691.59,1486.04 ; -683.71,1485.65 -631.67,1485.65 ; -630.85,1484.83 -630.85,1594.47
  other v1: -846.52,593.92 -643.31,1607.21 -621.28,1614.22
VBUS: C204.1 C205.2 C206.2 C207.2 C208.2 CON101.A4B9 CON101.B4A9 D105.K J202.40 U101.61@-316.54,1224.41 U201.1 U201.4 U202.1 U202.3 | length 2908.5
  Top Layer 1 w11.81: U202.3@-771.65,302.75 -771.65,343.73 ; D105.K@-368.1,364.64 -364.33,368.4 v1@-339.12,393.61 ; v1(-350.15,1221.7) -348.79,1223.05 -317.89,1223.05 U101.61@-316.54,1224.41 ; -299.57,399.08 -297.65,397.15 C204.1@-270.59,370.1
  Top Layer 1 w19.68: U201.1@-571.95,512.48 -571.79,512.64 -536.85,512.64 v1(-536.71,512.78)
  Top Layer 1 w23.62: C208.2@-698.18,342.11 v1@-675.59,342.11 ; -689.17,343.73 -687.51,345.39 v1(-673.19,359.71) -673.19,338.13 v1(-673.48,337.84) ; CON101.A4B9@-607.87,272.15 -607.87,309.82 ; CON101.B4A9@-418.9,278.98 -418.9,311.6 -418.01,312.49
  Top Layer 1 w30: J202.40@-963.39,53.94 -901.5,115.82 -901.5,222.53 -870.49,253.54 -870.49,253.92 -852.67,271.74 -852.67,320.47 -827.74,345.39 -687.51,345.39 -682.73,345.39 -678.76,349.36 ; v1(-673.48,337.84) -659.29,323.65 -621.71,323.65 -607.87,309.82 ; U201.4@-465.65,437.68 -328.56,437.68 -259.02,437.68 C204.1@-235.71,414.37 ; -418.01,312.49 -400.05,330.45 -372.9,330.45 -364.33,339.01 -364.33,368.4 v1@-364.33,397.15 ; v1@-360.33,397.15 -297.65,397.15 C204.1@-246.03,397.15 ; -278.88,436.9 C204.1@-246.03,404.05
  POWER3 w11.81: -536.71,446.41 v1(-536.71,512.78) ; v1(-350.15,1221.7) -350.15,1127.42 -305.32,1082.59 -305.32,915.54 -267.44,877.66 -267.44,804.11 -236.02,772.68 -236.02,740.12 -313.85,662.29 -313.85,469.21 -341.13,441.93
  POWER3 w23.62: -382.08,444.97 -380.37,443.26 -360.11,423 ; -360.11,437.44 -360.11,423 ; -358.35,421.25 -360.11,423 ; -345.61,446.41 -341.13,441.93 -336.64,437.44 -336.64,403.89 -360.11,403.89 -360.11,423
  POWER3 w30: v1@-673.19,338.13 v1(-673.19,359.71) -673.19,390.05 -619.98,443.26 -380.37,443.26 -342.85,443.26
  other v1: -360.11,400.77 -336.44,400.77
VDD_EXT: C113.2 C212.1 CON201.11 J202.37 K102.3 K102.4 R108.1 R205.2 R206.2 U101.24@-206.3,1102.36 | length 3366
  Top Layer 1 w7.87: U101.24@-206.3,1102.36 U101.24@-175.08,1102.36
  Top Layer 1 w15.75: v1(-265.37,756.48) -215.16,756.48 ; K102.4@-215.16,814.96 -215.16,767.13 -215.16,756.48 ; v1(-193.26,606.78) -194.01,607.53 -194.01,608.77 -215.16,629.92 -215.16,756.48
  Top Layer 1 w19.68: U101.24@-175.08,1102.36 v1(-159.14,1120.55)
  POWER3 w7.87: -594.41,753.27 -586.78,745.64 ; -583.07,745.31 -575.44,752.94
  POWER3 w10: v1(-773.38,1734.46) -749.31,1710.39 -704.85,1710.39 -644.16,1649.69 -552.84,1649.69 -533.8,1630.65 v1(-533.8,1592.41) ; v1(-583.73,685.5) -584.96,686.73 -584.96,745.64 -584.96,753.77 -582.25,756.48
  POWER3 w15.75: J202.37@-963.39,353.94 -902.65,414.67 -902.65,594.42 -740.59,756.48 -594.41,756.48 -582.25,756.48 v1(-265.37,756.48) ; v1(-266.35,1519.38) -206.3,1459.33 -206.3,1253.94 -159.14,1206.77 v1(-159.14,1120.55) -159.14,1119.48 -137.67,1098.01 -137.67,662.37 v1(-193.26,606.78)
  Bottom Layer 4 w10: v1(-773.38,1734.46) -772.46,1733.54 -772.46,1707.9 R205.2@-771.54,1706.98 ; v1(-583.73,685.5) -581.88,687.36 -581.88,704.07 R108.1@-579.27,706.67
  Bottom Layer 4 w11.81: -543.23,1746.37 -542.91,1746.68 CON201.11@-542.91,1786.42
  Bottom Layer 4 w15.75: C212.1@-586.18,1659.93 -586.09,1660.02 -586.09,1701.75 R206.2@-586,1701.84 -586.14,1701.98 -586.14,1703.46 -543.23,1746.37 ; C212.1@-584.93,1661.18 -534.55,1610.8 -534.55,1593.17 -460.77,1519.38 v1(-266.35,1519.38) ; C113.2@-223.24,1174.53 -219.3,1174.55 -217.78,1174.55 -164.81,1124.02 -161.12,1120.5 v1(-159.14,1120.55)
WAKEUP0: J201.1 U101.101@-655.12,1084.65 | length 1460.9
  Top Layer 1 w7.87: U101.101@-655.12,1084.65 -655.12,1064.65 -652.81,1062.34 -652.62,1062.15 ; -652.62,1062.15 v1(-640.31,1049.85) ; -650.79,1062.13 U101.101@-650.79,1082.13 ; v1(-467.72,896.64) -447.95,876.88 -302.75,876.88 -282.57,856.71 -194.86,856.71 -152.71,814.55 -152.71,395.45 -127.37,370.11 -127.37,117.92 J201.1@-63.39,53.94
  POWER3 w7.87: v1(-640.31,1049.85) -591.37,1049.85 -467.72,926.19 v1(-467.72,896.64)
pads on no net: ANT103.3 ANT103.4 CON101.0@-399.61,215.26 CON101.0@-627.17,215.26 CON101.A8 CON101.B8 CON102.0@-362.99,96.75 CON102.0@-362.99,331.99 CON102.0@-462.99,96.75 CON102.0@-462.99,331.99 CON102.0@-562.99,96.75 CON102.0@-562.99,331.99 CON102.0@-562.99,490.45 CON102.6 CON201.1 CON201.6 CON201.7 CON201.9 CON201.10 CON201.12 CON201.14 CON201.16 CON201.18 CON201.20 CON201.22 CON201.23 CON201.24 D101. D102. D103. D104. D105. D106. D107. J201.21 J201.22 J201.23 J201.24 J201.25 J201.26 J201.27 J201.28 J201.29 J201.30 J201.31 J201.32 J201.33 J201.34 J201.35 J201.36 J201.37 J201.38 J201.39 J201.40 J202.1 Q101. U101. U101.1@-804.72,1578.74 U101.2@-804.72,1535.43 U101.3 U101.4 U101.5@-804.72,1405.51 U101.6@-804.72,1362.2 U101.7@-804.72,1318.9 U101.8@-804.72,1275.59 U101.9@-804.72,1232.28 U101.10@-804.72,1188.98 U101.11@-804.72,1145.67 U101.12@-804.72,1102.36 U101.13@-804.72,1059.05 U101.14@-686.61,990.16 U101.15@-643.31,990.16 U101.16@-600,990.16 U101.17@-556.69,990.16 U101.18@-513.39,990.16 U101.19@-470.08,990.16 U101.20@-426.77,990.16 U101.21 U101.22 U101.23 U101.24@-222.05,1102.36 U101.25@-222.05,1145.67 U101.26@-222.05,1188.98 U101.27@-222.05,1232.28 U101.28@-222.05,1275.59 U101.29@-222.05,1318.9 U101.30@-222.05,1362.2 U101.31@-222.05,1405.51 U101.32@-222.05,1448.82 U101.33@-222.05,1492.13 U101.34@-222.05,1535.43 U101.35@-222.05,1578.74 U101.36@-340.16,1647.64 U101.37@-383.46,1647.64 U101.38@-426.77,1647.64 U101.39@-470.08,1647.64 U101.40@-513.39,1647.64 U101.41@-556.69,1647.64 U101.42@-600,1647.64 U101.43@-643.31,1647.64 U101.44 U101.45@-710.24,1507.87 U101.46@-710.24,1460.63 U101.47@-710.24,1413.39 U101.48@-710.24,1366.14 U101.49@-710.36,1318.45 U101.50@-710.36,1271.2 U101.51@-710.36,1223.96 U101.52@-710.36,1176.72 U101.53@-710.36,1129.47 U101.54@-607.87,1084.65 U101.55@-560.63,1084.65 U101.56@-513.39,1084.64 U101.57@-466.14,1084.65 U101.58@-418.9,1084.65 U101.59@-316.54,1129.92 U101.60@-316.54,1177.16 U101.61@-316.54,1224.41 U101.62@-316.54,1271.65 U101.63@-316.54,1318.9 U101.64@-316.54,1366.14 U101.65@-316.54,1413.39 U101.66@-316.54,1460.63 U101.67@-316.54,1507.87 U101.68 U101.69 U101.70@-513.39,1553.15 U101.71@-560.63,1553.15 U101.72@-607.87,1553.15 U101.73@-639.37,1484.25 U101.74 U101.75 U101.76 U101.77 U101.78@-639.37,1248.03 U101.79@-639.37,1200.79 U101.80@-639.37,1153.54 U101.81@-387.4,1153.54 U101.82@-387.4,1200.79 U101.83@-387.4,1248.03 U101.84@-387.4,1295.28 U101.85@-387.4,1342.52 U101.86@-387.4,1389.76 U101.87 U101.88@-387.4,1484.25 U101.89@-548.82,1389.76 U101.90@-548.82,1318.9 U101.91@-548.82,1248.03 U101.92@-477.95,1248.03 U101.93@-477.95,1318.9 U101.94@-477.95,1389.76 U101.95@-729.92,990.16 U101.96@-296.85,990.16 U101.97 U101.98 U101.99 U101.100 U101.101@-655.12,1084.65 U101.102 U101.103 U101.104 U101.105 U101.106 U101.107@-560.63,1153.54 U101.108 U101.109 U102. U102.0 U102.2 U102.4 U102.5

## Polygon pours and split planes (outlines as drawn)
GND on GND2 "NONET_L-01_P-001" (solid, remove dead copper, pour order 0): 0,0 -1026.77,0 -1026.77,2007.87 0,2007.87
GND on Bottom Layer 4 "NONET_L-01_P-001" (solid, remove dead copper, pour order 2): 0,0 -1026.77,0 -1026.77,2007.87 0,2007.87
GND on POWER3 "NONET_L-01_P-001" (solid, remove dead copper, pour order 1): 0,0 -1026.77,0 -1026.77,2007.87 0,2007.87
GND on Top Layer 1 "NONET_L-01_P-001" (solid, remove dead copper, pour order 3): 0,0 -1026.77,0 -1026.77,2007.87 0,2007.87

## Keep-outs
Keep-Out Layer:
  lines w7.87: -1026.77,0 -1026.77,2401.57 0,2401.57 0,0 -1026.77,0 ; -1026.77,0 -1026.77,0

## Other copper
Top Layer 1:
  pour cut-out: -392.73,380.49 -363.84,380.49 ccw(c-363.84,382.48) -362.44,381.07 ccw(c-334.29,352.92) -374.1,352.92 -374.1,350.07 -394.19,350.07 ccw(c-394.19,324.12) -412.54,342.47
  pour cut-out: -230.75,1063.79 -235.37,1068.41 -300.05,1068.41 -300.05,1062.64 -308.14,1054.55 -296.59,1043 -254.62,1043
  pour cut-out: -239.76,1255.39 -290.59,1255.39 -296.77,1261.57 -294.93,1263.41 -294.93,1281.5 -226.85,1281.5 -221.77,1286.57
  pour cut-out: -498.58,1575.37 -498.58,1604.33 -488.91,1614 -483.36,1608.45 -483.36,1570.67 -473.37,1560.68
  pour cut-out: -619.28,690.22 -619.15,683.99 -638.96,660.49 -651.03,680.86 -658.79,700.35
  pour cut-out: -660.1,1340.35 -660.1,1297.49 -424.65,1297.49 -424.65,1340.35
  pour cut-out: -671.34,408.33 -663.72,408.33 -655.72,416.33 -679.38,416.33
  pour cut-out: -646.33,1173.42 -609.5,1173.42 -609.5,1460.78 -646.33,1460.78
  pour cut-out: -732.92,1291.49 -690.06,1291.49 -690.06,1578.85 -732.92,1578.85
  pour cut-out: -699.7,1578.04 -699.7,1528.22 -464.25,1528.22 -464.25,1578.04
  pour cut-out: -659.77,1413.94 -659.77,1371.09 -424.32,1371.09 -424.32,1413.94
  pour cut-out: -668.35,1272.37 -668.35,1229.51 -432.9,1229.51 -432.9,1272.37
  pour cut-out: -601.64,1735.71 -607.34,1741.41 -713.93,1741.41 -744.2,1711.13 -729.92,1696.85 -729.92,1609.72 -645.41,1609.72 -643.31,1607.61
  pour cut-out: -627.43,1220.23 -627.43,1177.37 -391.98,1177.37 -391.98,1220.23
  pour cut-out: -407.95,1458.79 -450.81,1458.79 -450.81,1149.51 -407.95,1149.51
  pour cut-out: -738.05,1340.23 -785.61,1340.23 -785.61,1306.7 -716.23,1306.7 -716.23,1291.65
  pour cut-out: -384.59,503.27 -426.73,503.27 -426.73,543.61 -384.64,543.61 -384.64,559.35 -366.28,559.35 -366.28,512.08 -371.67,512.08
  pour cut-out: -824.46,563.45 -743.41,563.45 -742.89,562.92 -756.31,549.51 -816.86,549.51 -822.5,555.14
  pour cut-out: -898.32,1250.41 -947.63,1286.63 -890.54,1283.15
  pour cut-out: -694.39,995.74 -743.71,1031.96 -686.61,1028.48
  pour cut-out: -344.22,1060.9 -377.42,1070.72 -385.83,1207.69 -288.85,1202.63 -288.85,1104.46
  pour cut-out: -344.22,1576.9 -357.49,1568.08 -336.31,1543.3 -330.85,1547.01
  pour cut-out: -1035.27,232.95 -902.15,232.95 -891.19,221.99 -891.19,179.68 -942.96,179.68 -943.06,179.77
Bottom Layer 4:
  pour cut-out: -348.1,558.25 -348.47,557.87 -504.07,557.87 -504.07,616.24 cw(c-498.15,616.24) -502.33,620.43 ccw(c-496.06,626.7) -496.06,617.83 -342.29,617.83
  pour cut-out: -743.09,852.36 -725,852.36 -708.78,868.58 -733.4,893.2 -734.7,893.2 -750.1,877.8
  pour cut-out: -780.55,1155.42 -806.71,1181.57 -806.77,1181.57 -806.77,1166.57 -816.77,1156.57 -802.85,1142.66 -793.31,1142.66
  pour cut-out: -379.05,1255.69 -379.57,1256.21 -399.96,1256.21 -399.96,1273.38 -396.77,1276.57 -391.76,1271.57 -349.4,1271.57
  pour cut-out: -658.99,1684.65 -640.75,1682.03 -627.83,1689.27 -640.75,1696.89 -666.13,1701.13
  pour cut-out: -541.16,1356.37 -522.77,1355.16 -528.4,1369.13 -551.34,1365.79
  pour cut-out: -503.39,728.96 -503.94,716.68 -492.96,720.15 -503.39,738.8
  pour cut-out: -251.1,919.05 -348.84,858.86 -388.96,935.7 -293.84,949.78
Multi-Layer:
  pour cut-out: -920.47,0 -920.47,2007.26 -922,2008.79 -1026.77,2008.79 -1026.77,0
  pour cut-out: -106.3,0 -106.3,2007.26 -104.77,2008.79 0,2008.79 0,0

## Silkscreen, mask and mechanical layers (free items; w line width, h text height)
Top Overlay:
  text "C108" at -220.87,1943.66 h40
  text "C106" at -217.32,1906.57 h40 r90
  text "C120" at -108.27,1906.57 h40 r90
  text "GNSS" at -589.76,1801.57 h60 r90
  text "Cat.1" at -434.65,1799.66 h60 r90
  text "PWRKEY" at -866.14,851.57 h60
  text "RST" at -561.77,851.57 h60
  text "BOOT" at -326.77,851.57 h60
  text "R201" at -873.65,564.31 h60
  text "PWR" at -881.77,153.54 h60
  text "NET" at -273.23,153.54 h60
Bottom Overlay:
  rectangle: -193.94,2373.57 -143.94,2381.57
  rectangle: -886.77,2373.57 -836.77,2381.57
  rectangle: -771.77,2373.57 -721.77,2381.57
  rectangle: -656.77,2373.57 -606.77,2381.57
  rectangle: -541.77,2373.57 -491.77,2381.57
  rectangle: -426.77,2373.57 -376.77,2381.57
  rectangle: -311.77,2373.57 -261.77,2381.57
  rectangle: -311.77,2061.57 -261.77,2069.57
  rectangle: -426.77,2061.57 -376.77,2069.57
  rectangle: -541.77,2061.57 -491.77,2069.57
  rectangle: -656.77,2061.57 -606.77,2069.57
  rectangle: -771.77,2061.57 -721.77,2069.57
  rectangle: -193.94,2061.57 -143.94,2069.57
  region: -878.77,2336.57 -878.77,2381.57 -886.77,2381.57 -886.77,2336.57
  region: -886.77,2291.57 -886.77,2249.07 -878.77,2249.07 -878.77,2291.57
  region: -878.77,2151.57 -878.77,2194.07 -886.77,2194.07 -886.77,2151.57
  region: -878.77,2061.57 -878.77,2106.57 -886.77,2106.57 -886.77,2061.57
  region: -152.23,2291.57 -152.23,2249.07 -144.23,2249.07 -144.23,2291.57
  region: -144.23,2151.57 -144.23,2194.07 -152.23,2194.07 -152.23,2151.57
  region: -144.23,2336.57 -144.23,2381.57 -152.23,2381.57 -152.23,2336.57
  region: -144.23,2061.57 -144.23,2106.57 -152.23,2106.57 -152.23,2061.57
  rectangle: -886.77,2061.57 -836.77,2069.57
  text "P19" at -911.77,1926.57 h60 r270
  text "P18" at -155.74,1921.57 h60 r270
  text "P17" at -155.74,1806.57 h60 r270
  text "P20" at -909.04,1802.17 h60 r270
  text "P16" at -115.52,1731.57 h60
  text "P21" at -771.77,1731.33 h60
  text "P15" at -115.52,1631.57 h60
  text "P22" at -771.77,1631.33 h60
  text "P14" at -115.52,1531.57 h60
  text "P23" at -771.77,1531.33 h60
  text "YYWW" at -290,1530 h60
  text "S/C" at -455.64,1527.24 h60
  text "P13" at -115.52,1431.57 h60
  text "P24" at -771.77,1431.33 h60
  text "VCAM" at -778.56,1376.57 h40 r270
  text "P12" at -115.52,1331.57 h60
  text "P25" at -771.77,1331.33 h60
  text "P11" at -115.52,1231.57 h60
  text "P26" at -771.77,1231.33 h60
  text "USB-" at -365.37,1166.57 h40
  text "P10" at -115.52,1131.57 h60
  text "M_TX" at -771.77,1131.33 h60
  text "USB+" at -365.37,1096.57 h40
  text "P9" at -115.52,1031.57 h60
  text "M_RX" at -771.77,1031.33 h60
  text "Cat.1-PICO" at -254.01,988.47 h100
  text "P8" at -115.52,931.57 h60
  text "D_TX" at -771.77,931.33 h60
  text "NT26x-A1_V02" at -281.42,923.1 h60
  text "P7" at -115.52,831.57 h60
  text "D_RX" at -771.77,831.33 h60
  text "GND" at -115.52,731.57 h60
  text "GND" at -771.77,731.33 h60
  text "P6" at -115.52,631.57 h60
  text "P27" at -771.77,631.33 h60
  text "P5" at -115.52,531.57 h60
  text "P28" at -771.77,531.33 h60
  text "P4" at -115.52,431.57 h60
  text "3.3V" at -771.77,431.33 h60
  text "(OUT)" at -811.56,391.57 h47.24
  text "P3" at -115.52,331.57 h60
  text "VEXT" at -771.77,331.33 h60
  text "GND" at -115.52,231.57 h60
  text "GND" at -771.77,231.33 h60
  text "P2" at -115.52,131.57 h60
  text "3.8V" at -771.77,131.33 h60
  text "P1" at -115.52,31.57 h60
  text "5V" at -771.77,31.33 h60
Mechanical 1:
  lines w5: -513.39,0 -513.39,2411.03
